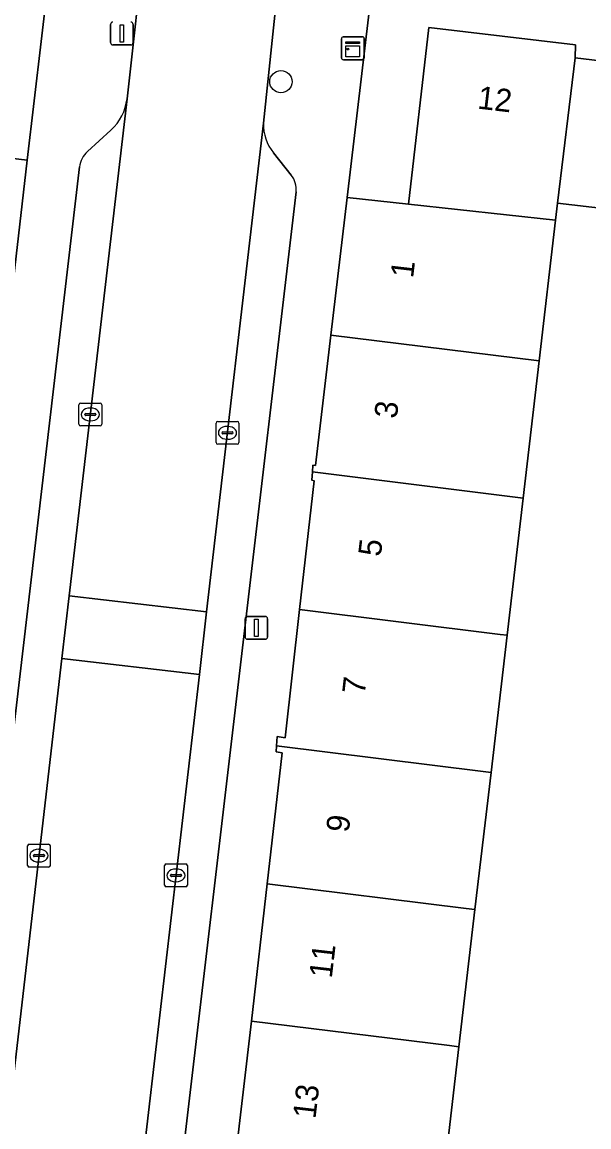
# Model space of a CAD drawing. Extents: x 161241 to 161758, y 384138 to 384885.
# Drawn here: x 161457.14 to 161481.96, y 384586.99 to 384635.36 of the extents above; entities that cross this region are included whole.
import ezdxf

# ---------------------------------------------------------------- set-up
doc = ezdxf.new("R2010")
doc.units = 0
for name, color, linetype in [('IMGEO_Boom', 7, 'Continuous'), ('IMGEO_Erf', 7, 'Continuous'), ('IMGEO_Kast', 7, 'Continuous'), ('IMGEO_Kolk', 7, 'Continuous'), ('IMGEO_Lichtmast', 7, 'Continuous'), ('IMGEO_Pand', 7, 'Continuous'), ('IMGEO_Pand_nummerreeks', 7, 'Continuous'), ('IMGEO_Parkeervlak_open', 7, 'Continuous'), ('IMGEO_Rijbaan_lokaal_open', 7, 'Continuous'), ('IMGEO_Voetpad_open', 7, 'Continuous')]:
    doc.layers.add(name, color=color, linetype=linetype)

msp = doc.modelspace()

# ---------------------------------------------------------------- linework, layer by layer
at = {"layer": 'IMGEO_Boom'}
msp.add_circle((161468.474, 384632.749), 0.489, dxfattribs=at)
at = {"layer": 'IMGEO_Erf'}
for points in [[(161454.687, 384629.637), (161457.357, 384629.317), (161458.589, 384639.718), (161400.088, 384646.416)], [(161472.604, 384638.05), (161471.374, 384627.684), (161474.064, 384627.391), (161474.958, 384635.124), (161481.38, 384634.367), (161481.361, 384633.795), (161490.094, 384632.743)], [(161489.365, 384626.402), (161480.594, 384627.428), (161480.507, 384626.683), (161479.786, 384620.526), (161479.083, 384614.52), (161478.38, 384608.515), (161477.677, 384602.51), (161476.974, 384596.505), (161476.271, 384590.5), (161475.503, 384583.942)]]:
    msp.add_lwpolyline(points, dxfattribs=at)
at = {"layer": 'IMGEO_Kast'}
for p, q in [((161471.2, 384634.71), (161472.041, 384634.71)), ((161472.041, 384634.71), (161471.2, 384634.71)), ((161471.125, 384633.785), (161471.125, 384634.626)), ((161471.125, 384634.626), (161471.125, 384633.785)), ((161472.125, 384634.635), (161472.125, 384633.794)), ((161472.125, 384633.794), (161472.125, 384634.635)), ((161472.05, 384633.71), (161471.209, 384633.71)), ((161471.209, 384633.71), (161472.05, 384633.71))]:
    msp.add_line(p, q, dxfattribs=at)
for points in [[(161471.32, 384634.5), (161471.92, 384634.5), (161471.92, 384634.415), (161471.32, 384634.415), (161471.32, 384634.5)], [(161471.32, 384634.325), (161471.92, 384634.325), (161471.92, 384633.836), (161471.32, 384633.836), (161471.32, 384634.325)]]:
    msp.add_lwpolyline(points, dxfattribs=at)
msp.add_circle((161471.404, 384634.174), 0.0377, dxfattribs=at)
for centre, start, end in [((161471.203, 384634.632), 92.4484, 184.2845), ((161471.203, 384634.632), 92.4484, 184.2845), ((161472.047, 384634.632), 2.4484, 94.2845), ((161472.047, 384634.632), 2.4484, 94.2845), ((161471.203, 384633.788), 182.4484, 274.2845), ((161471.203, 384633.788), 182.4484, 274.2845), ((161472.047, 384633.788), 272.4484, 4.2845), ((161472.047, 384633.788), 272.4484, 4.2845)]:
    msp.add_arc(centre, 0.0779, start, end, dxfattribs=at)
at = {"layer": 'IMGEO_Kolk'}
for p, q in [((161459.623, 384617.755), (161459.623, 384618.607)), ((161459.698, 384618.681), (161460.55, 384618.681)), ((161459.925, 384618.224), (161460.323, 384618.224)), ((161460.111, 384618.461), (161460.136, 384618.461)), ((161460.624, 384618.607), (161460.624, 384617.755)), ((161459.882, 384618.175), (161459.882, 384618.187)), ((161460.32, 384618.138), (161459.922, 384618.138)), ((161460.134, 384617.901), (161460.109, 384617.901)), ((161460.366, 384618.187), (161460.366, 384618.175)), ((161465.633, 384616.95), (161465.633, 384617.802)), ((161465.708, 384617.876), (161466.56, 384617.876)), ((161466.634, 384617.802), (161466.634, 384616.95)), ((161460.55, 384617.681), (161459.698, 384617.681)), ((161465.892, 384617.37), (161465.892, 384617.382)), ((161466.33, 384617.333), (161465.932, 384617.333)), ((161465.935, 384617.419), (161466.333, 384617.419)), ((161466.121, 384617.656), (161466.146, 384617.656)), ((161466.376, 384617.382), (161466.376, 384617.37)), ((161466.56, 384616.876), (161465.708, 384616.876)), ((161466.144, 384617.096), (161466.119, 384617.096)), ((161457.447, 384599.368), (161458.299, 384599.368)), ((161457.372, 384598.442), (161457.372, 384599.294)), ((161457.674, 384598.911), (161458.072, 384598.911)), ((161457.86, 384599.148), (161457.885, 384599.148)), ((161458.373, 384599.294), (161458.373, 384598.442)), ((161457.631, 384598.862), (161457.631, 384598.874)), ((161458.069, 384598.825), (161457.671, 384598.825)), ((161457.883, 384598.588), (161457.858, 384598.588)), ((161458.115, 384598.874), (161458.115, 384598.862)), ((161463.376, 384597.576), (161463.376, 384598.428)), ((161463.451, 384598.502), (161464.303, 384598.502)), ((161464.377, 384598.428), (161464.377, 384597.576)), ((161458.299, 384598.368), (161457.447, 384598.368)), ((161463.635, 384597.996), (161463.635, 384598.008)), ((161464.073, 384597.959), (161463.675, 384597.959)), ((161463.678, 384598.045), (161464.076, 384598.045)), ((161463.864, 384598.282), (161463.889, 384598.282)), ((161464.119, 384598.008), (161464.119, 384597.996)), ((161464.303, 384597.502), (161463.451, 384597.502)), ((161463.887, 384597.722), (161463.862, 384597.722))]:
    msp.add_line(p, q, dxfattribs=at)
for points in [[(161459.623, 384617.755), (161459.623, 384618.607)], [(161459.698, 384618.681), (161460.55, 384618.681)], [(161460.624, 384618.607), (161460.624, 384617.755)], [(161465.633, 384616.95), (161465.633, 384617.802)], [(161465.708, 384617.876), (161466.56, 384617.876)], [(161466.634, 384617.802), (161466.634, 384616.95)], [(161460.55, 384617.681), (161459.698, 384617.681)], [(161466.56, 384616.876), (161465.708, 384616.876)], [(161457.447, 384599.368), (161458.299, 384599.368)], [(161457.372, 384598.442), (161457.372, 384599.294)], [(161458.373, 384599.294), (161458.373, 384598.442)], [(161463.376, 384597.576), (161463.376, 384598.428)], [(161463.451, 384598.502), (161464.303, 384598.502)], [(161464.377, 384598.428), (161464.377, 384597.576)], [(161458.299, 384598.368), (161457.447, 384598.368)], [(161464.303, 384597.502), (161463.451, 384597.502)]]:
    msp.add_lwpolyline(points, dxfattribs=at)
for centre, radius, start, end in [((161459.7, 384618.605), 0.0765, 91.552, 178.448), ((161459.7, 384618.605), 0.0765, 91.552, 178.448), ((161459.922, 384618.184), 0.0403, 85.8775, 175.7526), ((161460.327, 384618.186), 0.0386, 1.7309, 96.639), ((161460.548, 384618.605), 0.0765, 1.552, 88.448), ((161460.548, 384618.605), 0.0765, 1.552, 88.448), ((161459.7, 384617.757), 0.0765, 181.552, 268.448), ((161459.7, 384617.757), 0.0765, 181.552, 268.448), ((161459.919, 384618.174), 0.0366, 178.938, 274.7102), ((161460.323, 384618.181), 0.043, 264.8664, 352.4533), ((161460.548, 384617.757), 0.0765, 271.552, 358.448), ((161460.548, 384617.757), 0.0765, 271.552, 358.448), ((161465.71, 384617.8), 0.0765, 91.552, 178.448), ((161465.71, 384617.8), 0.0765, 91.552, 178.448), ((161466.558, 384617.8), 0.0765, 1.552, 88.448), ((161466.558, 384617.8), 0.0765, 1.552, 88.448), ((161465.932, 384617.379), 0.0403, 85.8775, 175.7526), ((161465.929, 384617.369), 0.0366, 178.938, 274.7102), ((161466.333, 384617.376), 0.043, 264.8664, 352.4533), ((161466.337, 384617.381), 0.0386, 1.7309, 96.639), ((161465.71, 384616.952), 0.0765, 181.552, 268.448), ((161465.71, 384616.952), 0.0765, 181.552, 268.448), ((161466.558, 384616.952), 0.0765, 271.552, 358.448), ((161466.558, 384616.952), 0.0765, 271.552, 358.448), ((161457.449, 384599.292), 0.0765, 91.552, 178.448), ((161457.449, 384599.292), 0.0765, 91.552, 178.448), ((161458.297, 384599.292), 0.0765, 1.552, 88.448), ((161458.297, 384599.292), 0.0765, 1.552, 88.448), ((161457.671, 384598.871), 0.0403, 85.8775, 175.7526), ((161458.076, 384598.873), 0.0386, 1.7309, 96.639), ((161457.449, 384598.444), 0.0765, 181.552, 268.448), ((161457.449, 384598.444), 0.0765, 181.552, 268.448), ((161457.668, 384598.861), 0.0366, 178.938, 274.7102), ((161458.072, 384598.868), 0.043, 264.8664, 352.4533), ((161458.297, 384598.444), 0.0765, 271.552, 358.448), ((161458.297, 384598.444), 0.0765, 271.552, 358.448), ((161463.453, 384598.426), 0.0765, 91.552, 178.448), ((161463.453, 384598.426), 0.0765, 91.552, 178.448), ((161464.301, 384598.426), 0.0765, 1.552, 88.448), ((161464.301, 384598.426), 0.0765, 1.552, 88.448), ((161463.675, 384598.005), 0.0403, 85.8775, 175.7526), ((161463.672, 384597.995), 0.0366, 178.938, 274.7102), ((161464.076, 384598.002), 0.043, 264.8664, 352.4533), ((161464.08, 384598.007), 0.0386, 1.7309, 96.639), ((161463.453, 384597.578), 0.0765, 181.552, 268.448), ((161463.453, 384597.578), 0.0765, 181.552, 268.448), ((161464.301, 384597.578), 0.0765, 271.552, 358.448), ((161464.301, 384597.578), 0.0765, 271.552, 358.448)]:
    msp.add_arc(centre, radius, start, end, dxfattribs=at)
for centre, major_axis, ratio, start_param, end_param in [((161460.11, 384618.181), (-0.387, 0.002), 0.722429, 4.712389, 7.853982), ((161460.135, 384618.181), (-0.39, 0.002), 0.717154, 1.570796, 4.712389), ((161466.12, 384617.376), (-0.387, 0.002), 0.722429, 4.712389, 7.853982), ((161466.145, 384617.376), (-0.39, 0.002), 0.717154, 1.570796, 4.712389), ((161457.859, 384598.868), (-0.387, 0.002), 0.722429, 4.712389, 7.853982), ((161457.884, 384598.868), (-0.39, 0.002), 0.717154, 1.570796, 4.712389), ((161463.863, 384598.002), (-0.387, 0.002), 0.722429, 4.712389, 7.853982), ((161463.888, 384598.002), (-0.39, 0.002), 0.717154, 1.570796, 4.712389)]:
    msp.add_ellipse(centre, major_axis=major_axis, ratio=ratio, start_param=start_param, end_param=end_param, dxfattribs=at)
at = {"layer": 'IMGEO_Lichtmast'}
for p, q in [((161461.012, 384634.458), (161461.012, 384635.258)), ((161461.012, 384635.258), (161461.012, 384634.458)), ((161462.002, 384635.258), (161462.002, 384634.458)), ((161462.002, 384634.458), (161462.002, 384635.258)), ((161461.902, 384634.358), (161461.112, 384634.358)), ((161461.112, 384634.358), (161461.902, 384634.358)), ((161466.901, 384608.437), (161466.901, 384609.237)), ((161466.901, 384609.237), (161466.901, 384608.437)), ((161467.001, 384609.337), (161467.791, 384609.337)), ((161467.791, 384609.337), (161467.001, 384609.337)), ((161467.891, 384609.237), (161467.891, 384608.437)), ((161467.891, 384608.437), (161467.891, 384609.237)), ((161467.791, 384608.337), (161467.001, 384608.337)), ((161467.001, 384608.337), (161467.791, 384608.337))]:
    msp.add_line(p, q, dxfattribs=at)
for points in [[(161461.432, 384635.233), (161461.582, 384635.233), (161461.582, 384634.483), (161461.432, 384634.483), (161461.432, 384635.233)], [(161467.321, 384609.212), (161467.471, 384609.212), (161467.471, 384608.462), (161467.321, 384608.462), (161467.321, 384609.212)]]:
    msp.add_lwpolyline(points, dxfattribs=at)
for centre, start, end in [((161461.112, 384635.258), 90, 180), ((161461.112, 384635.258), 90, 180), ((161461.902, 384635.258), 0, 90), ((161461.902, 384635.258), 360, 90), ((161461.112, 384634.458), 180, 270), ((161461.112, 384634.458), 180, 270), ((161461.902, 384634.458), 270, 0), ((161461.902, 384634.458), 270, 0), ((161467.001, 384609.237), 90, 180), ((161467.001, 384609.237), 90, 180), ((161467.791, 384609.237), 0, 90), ((161467.791, 384609.237), 360, 90), ((161467.001, 384608.437), 180, 270), ((161467.001, 384608.437), 180, 270), ((161467.791, 384608.437), 270, 0), ((161467.791, 384608.437), 270, 0)]:
    msp.add_arc(centre, 0.1, start, end, dxfattribs=at)
at = {"layer": 'IMGEO_Pand'}
for points in [[(161481.361, 384633.795), (161481.38, 384634.367), (161474.958, 384635.124), (161474.064, 384627.391), (161480.507, 384626.683), (161480.594, 384627.428)], [(161495.378, 384625.217), (161496.436, 384633.757), (161490.303, 384634.456), (161490.094, 384632.743), (161481.361, 384633.795), (161480.594, 384627.428), (161489.365, 384626.402), (161489.259, 384625.489), (161495.324, 384624.779)], [(161457.357, 384629.317), (161454.687, 384629.637), (161448.273, 384630.403), (161447.578, 384624.274), (161456.659, 384623.201)], [(161470.664, 384621.655), (161479.786, 384620.526), (161480.507, 384626.683), (161474.064, 384627.391), (161471.374, 384627.684)], [(161469.852, 384615.663), (161479.083, 384614.52), (161479.786, 384620.526), (161470.664, 384621.655), (161469.99, 384615.939), (161469.867, 384615.956)], [(161469.293, 384609.641), (161478.081, 384608.552), (161478.38, 384608.515), (161479.083, 384614.52), (161469.852, 384615.663), (161469.834, 384615.308), (161469.934, 384615.273)], [(161468.285, 384603.673), (161477.338, 384602.552), (161477.677, 384602.51), (161478.38, 384608.515), (161478.081, 384608.552), (161469.293, 384609.641), (161468.654, 384604.025), (161468.309, 384604.077)], [(161467.872, 384597.633), (161476.595, 384596.552), (161476.974, 384596.505), (161477.677, 384602.51), (161477.338, 384602.552), (161468.285, 384603.673), (161468.27, 384603.414), (161468.535, 384603.372)], [(161467.179, 384591.626), (161475.852, 384590.552), (161476.271, 384590.5), (161476.974, 384596.505), (161476.595, 384596.552), (161467.872, 384597.633)], [(161466.461, 384585.408), (161469.124, 384585.125), (161475.091, 384584.461), (161475.04, 384584), (161475.503, 384583.942), (161476.271, 384590.5), (161475.852, 384590.552), (161467.179, 384591.626)]]:
    msp.add_lwpolyline(points, close=True, dxfattribs=at)
at = {"layer": 'IMGEO_Parkeervlak_open'}
for points in [[(161456.155, 384584.108), (161458.88, 384607.496), (161459.201, 384610.247), (161461.735, 384631.999)], [(161467.711, 384630.934), (161465.22, 384609.545), (161464.9, 384606.794), (161462.171, 384583.365)], [(161461.027, 384630.63), (161460.001, 384629.696)], [(161468.925, 384628.66), (161468.145, 384629.632)], [(161459.649, 384629.015), (161454.735, 384587.127)], [(161464.207, 384586.016), (161469.135, 384627.927)]]:
    msp.add_lwpolyline(points, dxfattribs=at)
for centre, radius, start, end in [((161459.537, 384632.268), 2.214, 312.287, 353.0201), ((161469.666, 384630.862), 1.957, 177.9043, 218.9656), ((161460.745, 384628.88), 1.104, 132.3568, 172.9755), ((161468.16, 384628.044), 0.982, 353.1326, 38.8407)]:
    msp.add_arc(centre, radius, start, end, dxfattribs=at)
at = {"layer": 'IMGEO_Rijbaan_lokaal_open'}
for points in [[(161462.513, 384638.982), (161461.735, 384631.999), (161459.201, 384610.247), (161465.22, 384609.545), (161467.711, 384630.934)], [(161467.711, 384630.934), (161468.506, 384638.465)]]:
    msp.add_lwpolyline(points, dxfattribs=at)
for points in [[(161458.88, 384607.496), (161464.9, 384606.794), (161465.22, 384609.545), (161459.201, 384610.247)], [(161458.88, 384607.496), (161456.155, 384584.108), (161455.501, 384578.293), (161455.326, 384576.798), (161454.02, 384565.608), (161453.187, 384558.455), (161452.178, 384549.677), (161458.115, 384548.986), (161459.149, 384557.883), (161459.972, 384564.87), (161461.287, 384576.027), (161461.494, 384577.785), (161462.171, 384583.365), (161464.9, 384606.794)]]:
    msp.add_lwpolyline(points, close=True, dxfattribs=at)
at = {"layer": 'IMGEO_Voetpad_open'}
for points in [[(161462.513, 384638.982), (161458.589, 384639.718), (161457.357, 384629.317), (161456.659, 384623.201)], [(161461.735, 384631.999), (161462.513, 384638.982)], [(161466.461, 384585.408), (161467.179, 384591.626), (161467.872, 384597.633), (161468.535, 384603.372), (161468.27, 384603.414), (161468.285, 384603.673), (161468.309, 384604.077), (161468.654, 384604.025), (161469.293, 384609.641), (161469.934, 384615.273), (161469.834, 384615.308), (161469.852, 384615.663), (161469.867, 384615.956), (161469.99, 384615.939), (161470.664, 384621.655), (161471.374, 384627.684), (161472.604, 384638.05), (161468.506, 384638.465), (161467.711, 384630.934)], [(161460.001, 384629.696), (161461.027, 384630.63)], [(161468.145, 384629.632), (161468.925, 384628.66)], [(161454.735, 384587.127), (161459.649, 384629.015)], [(161469.135, 384627.927), (161464.207, 384586.016)]]:
    msp.add_lwpolyline(points, dxfattribs=at)
for centre, radius, start, end in [((161459.537, 384632.268), 2.214, 312.287, 353.0201), ((161469.666, 384630.862), 1.957, 177.9043, 218.9656), ((161460.745, 384628.88), 1.104, 132.3568, 172.9755), ((161468.16, 384628.044), 0.982, 353.1326, 38.8407)]:
    msp.add_arc(centre, radius, start, end, dxfattribs=at)

# ---------------------------------------------------------------- texts
at = {"layer": 'IMGEO_Pand_nummerreeks'}
for s, rotation, p in [('12', 353.2772, (161477.052, 384631.575)), ('1', 83.3712, (161474.263, 384624.125)), ('3', 83.3712, (161473.548, 384617.972)), ('5', 83.3712, (161472.846, 384611.933)), ('7', 83.3712, (161472.144, 384605.893)), ('9', 83.3712, (161471.442, 384599.854)), ('11', 83.3712, (161470.7, 384593.471)), ('13', 83.3712, (161469.986, 384587.319))]:
    msp.add_text(s, height=1, rotation=rotation, dxfattribs=at).set_placement(p)

doc.saveas('drawing.dxf')
